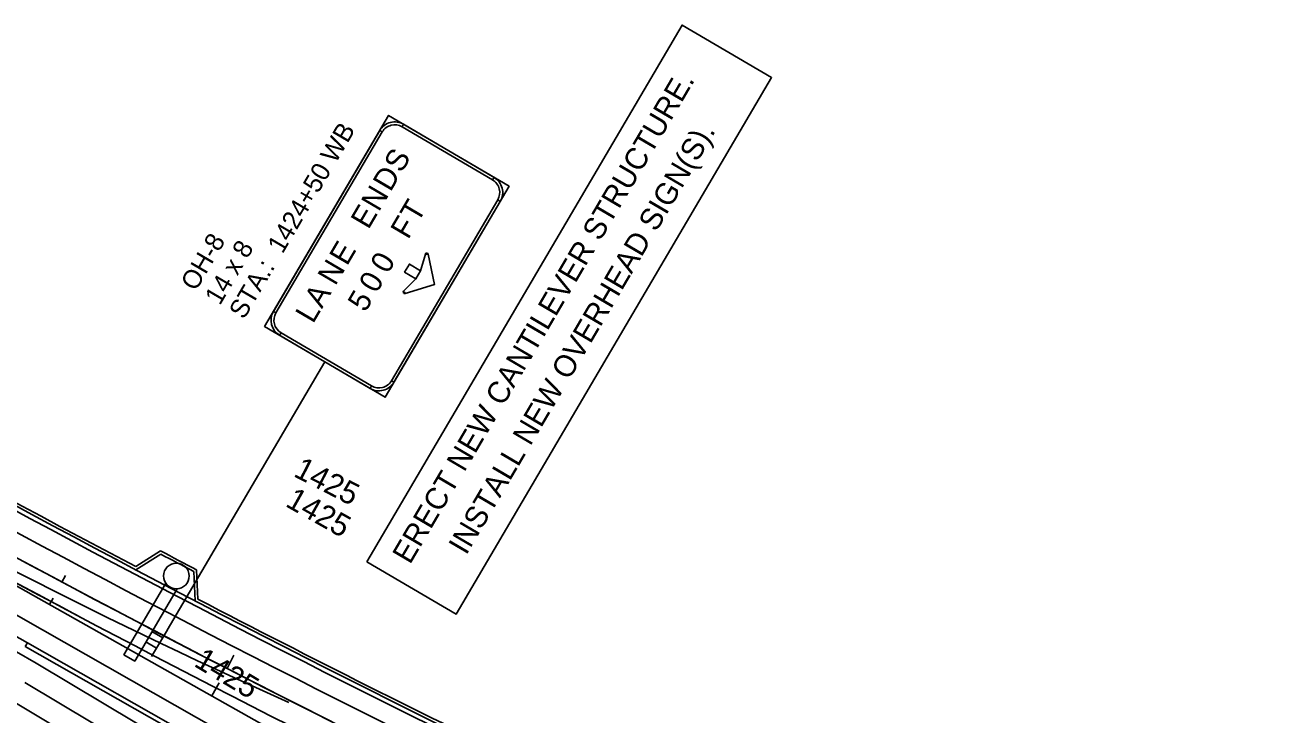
# Model space of a CAD drawing. Extents: x 2338610 to 2351914, y 366540 to 376484.
# Drawn here: x 2348627 to 2349299, y 368532 to 368902 of the extents above; entities that cross this region are included whole.
import ezdxf

# ---------------------------------------------------------------- set-up
doc = ezdxf.new("R2010")
doc.units = 0
for name, color, linetype in [('RD_HC_Cl', 7, 'Continuous'), ('RD_HC_CL_Rel', 7, 'Continuous'), ('RD_PD_Final_LnLine', 7, 'Continuous'), ('RD_PD_Final_TrvlWay', 7, 'Continuous'), ('RD_PD_MedBWall', 7, 'Continuous'), ('RD_PD_NOISE-WALL-GM', 7, 'Continuous'), ('RD_PD_PaveShd', 7, 'Continuous'), ('RD_PD_WallCut', 7, 'Continuous'), ('TR PM UNASSIGNED 3', 7, 'Continuous'), ('TR SN EXTRUDED PANEL SIGNS- MOUNTED OVERHEAD', 7, 'Continuous'), ('TR SN UNASSIGNED 7', 7, 'Continuous')]:
    doc.layers.add(name, color=color, linetype=linetype)

msp = doc.modelspace()

# ---------------------------------------------------------------- linework, layer by layer
at = {"layer": 'RD_HC_Cl'}
msp.add_arc((2349948.99, 371187.23), 2900, 239.17851, 245.9774, dxfattribs=at)
msp.add_arc((2349948.99, 371187.23), 2900, 239.17851, 245.9774, dxfattribs=at)
msp.add_arc((2349948.99, 371187.23), 2900, 239.17851, 245.9774, dxfattribs=at)
msp.add_arc((2349948.99, 371187.23), 2900, 239.17851, 245.9774, dxfattribs=at)
at = {"layer": 'RD_HC_CL_Rel'}
msp.add_line((2348500.93, 368669.16), (2349129.79, 368315.43), dxfattribs=at)
msp.add_arc((2351938.58, 374780.68), 7000, 240.642806, 245.882475, dxfattribs=at)
at = {"layer": 'RD_PD_Final_LnLine'}
msp.add_line((2348620.92, 368538.62), (2349820.78, 367822.75), dxfattribs=at)
for radius, start, end in [(7000, 239.178507, 245.882475), (7012, 239.178507, 242.089491), (7012, 240.642806, 243.703137)]:
    msp.add_arc((2351938.58, 374780.68), radius, start, end, dxfattribs=at)
at = {"layer": 'RD_PD_Final_TrvlWay'}
for p, q in [((2349153.03, 368283.92), (2348521.76, 368642.31)), ((2348626.93, 368549.01), (2349813.16, 367841.27))]:
    msp.add_line(p, q, dxfattribs=at)
msp.add_arc((2351938.58, 374780.68), 6988, 239.178507, 245.882475, dxfattribs=at)
at = {"layer": 'RD_PD_MedBWall'}
for radius in [6978, 6975.67]:
    msp.add_arc((2351938.58, 374780.68), radius, 239.178507, 245.882475, dxfattribs=at)
at = {"layer": 'RD_PD_NOISE-WALL-GM'}
for p, q in [((2348686.37, 368611.22), (2348699.71, 368619.65)), ((2348686.44, 368609.49), (2348699.78, 368617.92)), ((2348719.63, 368593.81), (2348718.96, 368609.57)), ((2348718.17, 368592.88), (2348717.5, 368608.64))]:
    msp.add_line(p, q, dxfattribs=at)
for radius, start, end in [(6974.17, 239.178507, 242.204196), (6960.5, 242.268979, 242.447832), (6962, 242.276108, 242.440704), (6974.17, 242.512616, 245.882475)]:
    msp.add_arc((2351938.58, 374780.68), radius, start, end, dxfattribs=at)
at = {"layer": 'RD_PD_PaveShd'}
for p, q in [((2348330.01, 368734.5), (2348633, 368559.35)), ((2348628.23, 368570.36), (2348516.82, 368633.61)), ((2348633, 368559.35), (2349320.08, 368149.43))]:
    msp.add_line(p, q, dxfattribs=at)
msp.add_arc((2351938.58, 374780.68), 6978, 239.178507, 245.882475, dxfattribs=at)
at = {"layer": 'RD_PD_WallCut'}
for p, q in [((2348627.08, 368568.34), (2348628.23, 368570.36)), ((2349148.1, 368275.22), (2348628.23, 368570.36)), ((2349148.1, 368275.22), (2348628.23, 368570.36)), ((2349146.94, 368273.19), (2348627.08, 368568.34))]:
    msp.add_line(p, q, dxfattribs=at)
at = {"layer": 'TR SN EXTRUDED PANEL SIGNS- MOUNTED OVERHEAD'}
for p, q in [((2348817.24, 368845.25), (2348818.59, 368844.46)), ((2348829.29, 368847.23), (2348830.08, 368848.58)), ((2348878.6, 368820.07), (2348877.81, 368818.72)), ((2348880.59, 368808.02), (2348881.94, 368807.23)), ((2348841.76, 368778.93), (2348842.51, 368778.72)), ((2348842.51, 368778.72), (2348843.28, 368778.89)), ((2348830.63, 368758.5), (2348830.08, 368759.05)), ((2348830.86, 368757.75), (2348830.63, 368758.5)), ((2348761.56, 368747.41), (2348760.21, 368748.21)), ((2348763.54, 368735.37), (2348764.34, 368736.71)), ((2348787.8, 368721.11), (2348703.2, 368577.16)), ((2348824.9, 368710.18), (2348823.56, 368710.98)), ((2348812.86, 368708.2), (2348812.07, 368706.85)), ((2348703.34, 368577.39), (2348694.88, 368562.99)), ((2348695.08, 368576.39), (2348700.81, 368573.03)), ((2348691.83, 368570.85), (2348697.58, 368567.47))]:
    msp.add_line(p, q, dxfattribs=at)
for points in [[(2348810.26, 368613.88), (2348979.5, 368901.85), (2349027.48, 368873.65), (2348858.24, 368585.68)], [(2348820.15, 368702.1), (2348886.69, 368815.31), (2348822, 368853.33), (2348755.46, 368740.12), (2348820.15, 368702.1), (2348820.15, 368702.1)], [(2348818.59, 368844.46), (2348761.56, 368747.41), (2348760.21, 368748.21), (2348817.24, 368845.25), (2348818.59, 368844.46), (2348818.59, 368844.46)], [(2348877.81, 368818.72), (2348829.29, 368847.23), (2348830.08, 368848.58), (2348878.6, 368820.07), (2348877.81, 368818.72), (2348877.81, 368818.72)], [(2348823.56, 368710.98), (2348880.59, 368808.02), (2348881.94, 368807.23), (2348824.9, 368710.18), (2348823.56, 368710.98), (2348823.56, 368710.98)], [(2348846.68, 368762.67), (2348843.28, 368778.89), (2348842.51, 368778.72), (2348841.76, 368778.93), (2348839.21, 368770), (2348836.63, 368765.62), (2348830.08, 368759.05), (2348830.63, 368758.5), (2348830.86, 368757.75), (2348846.68, 368762.67), (2348846.68, 368762.67)], [(2348830.57, 368769.19), (2348833.14, 368773.57), (2348839.21, 368770), (2348836.63, 368765.62), (2348830.57, 368769.19), (2348830.57, 368769.19)], [(2348764.34, 368736.71), (2348812.86, 368708.2), (2348812.07, 368706.85), (2348763.54, 368735.37), (2348764.34, 368736.71), (2348764.34, 368736.71)]]:
    msp.add_lwpolyline(points, close=True, dxfattribs=at)
msp.add_lwpolyline([(2348702.53, 368602.29), (2348680.01, 368563.97), (2348685.79, 368560.58), (2348708.57, 368599.34)], dxfattribs=at)
msp.add_circle((2348708.18, 368606.21), 6.89, dxfattribs=at)
for centre, radius, start, end in [((2348825.33, 368840.5), 9.38, 59.55676, 149.55697), ((2348825.33, 368840.5), 7.82, 59.55676, 149.55697), ((2348873.85, 368811.98), 7.82, 329.55682, 59.55703), ((2348873.85, 368811.98), 9.38, 329.55682, 59.55703), ((2348842.51, 368778.72), 0.782, 12.58194, 164.02958), ((2348830.63, 368758.5), 0.782, 135.08405, 286.5317), ((2348768.3, 368743.45), 9.38, 149.55697, 239.55661), ((2348768.3, 368743.45), 7.82, 149.55697, 239.55661), ((2348816.82, 368714.94), 7.82, 239.55661, 329.55682), ((2348816.82, 368714.94), 9.38, 239.55661, 329.55682)]:
    msp.add_arc(centre, radius, start, end, dxfattribs=at)
at = {"layer": 'TR SN UNASSIGNED 7'}
for p, q in [((2348646.79, 368602.96), (2348648.68, 368606.49)), ((2348640.03, 368590.91), (2348641.99, 368594.4)), ((2348735.38, 368556.57), (2348739.04, 368563.68)), ((2348727.19, 368541.88), (2348731.11, 368548.86))]:
    msp.add_line(p, q, dxfattribs=at)

# ---------------------------------------------------------------- texts
at = {"layer": 'TR PM UNASSIGNED 3'}
for s, p in [('STA.:  1424+50 WB', (2348744.44, 368743.43)), ('OH-8', (2348718.56, 368758.61)), ('14 x 8', (2348731.5, 368751.02))]:
    msp.add_text(s, height=10, rotation=59.60779, dxfattribs=at).set_placement(p)
at = {"layer": 'TR SN EXTRUDED PANEL SIGNS- MOUNTED OVERHEAD'}
for s, height, rotation, p in [('ERECT NEW CANTILEVER STRUCTURE.', 11.7187, 59.55684, (2348833.51, 368611.99)), ('INSTALL NEW OVERHEAD SIGN(S).', 11.7187, 59.55684, (2348863.63, 368616.98)), ('S', 11.73, 59.55676, (2348828.98, 368822.03)), ('D', 11.73, 59.55676, (2348823.02, 368811.89)), ('N', 11.73, 59.55676, (2348816.76, 368801.23)), ('E', 11.73, 59.55676, (2348811.17, 368791.72)), ('T', 11.73, 59.55676, (2348837.68, 368795.17)), ('F', 11.73, 59.55676, (2348832.5, 368786.36)), ('E', 11.73, 59.55676, (2348799.68, 368772.17)), ('0', 11.73, 59.55676, (2348821.64, 368767.88)), ('N', 11.73, 59.55676, (2348793.41, 368761.51)), ('0', 11.73, 59.55676, (2348815.5, 368757.43)), ('A', 11.73, 59.55676, (2348786.25, 368749.31)), ('5', 11.73, 59.55676, (2348809.54, 368747.29)), ('L', 11.73, 59.55676, (2348781.48, 368741.19))]:
    msp.add_text(s, height=height, rotation=rotation, dxfattribs=at).set_placement(p)
at = {"layer": 'TR SN UNASSIGNED 7'}
for rotation, p in [(332.76766, (2348770.47, 368659.97)), (330.64281, (2348766.09, 368643.92)), (329.17851, (2348717.02, 368558.14))]:
    msp.add_text('1425', height=12, rotation=rotation, dxfattribs=at).set_placement(p)

doc.saveas('drawing.dxf')
